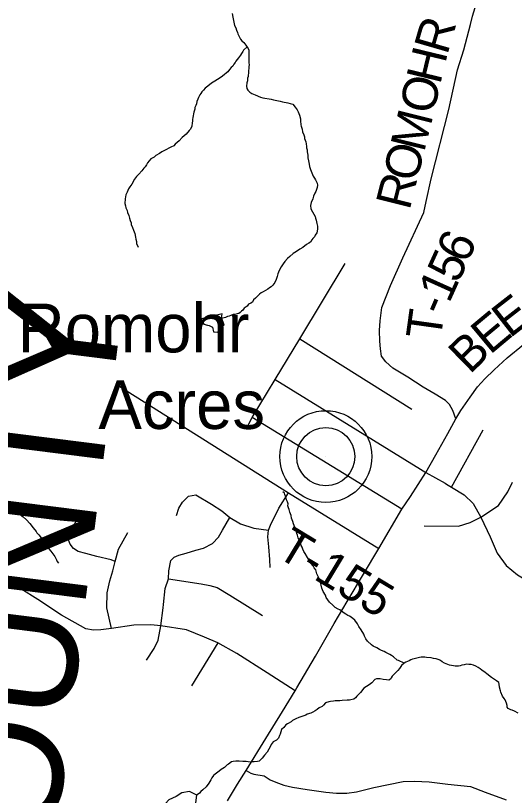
# Model space of a CAD drawing. Extents: x 0 to 34, y 0 to 22.
# Drawn here: x 6.117 to 6.521, y 17.744 to 18.376 of the extents above; entities that cross this region are included whole.
import ezdxf

# ---------------------------------------------------------------- set-up
doc = ezdxf.new("R2010")
doc.units = 0
for name, color, linetype in [('GM_X_County_Road', 7, 'Continuous'), ('GM_X_County_Road_Text', 7, 'Continuous'), ('GM_X_County_Text', 7, 'Continuous'), ('GM_X_Minor_Lake', 7, 'Continuous'), ('GM_X_Minor_River', 7, 'Continuous'), ('GM_X_Township_Road', 7, 'Continuous'), ('GM_X_Township_Road_Text', 7, 'Continuous'), ('GM_X_Unincorporated', 7, 'Continuous'), ('GM_X_Unincorporated_Location', 7, 'Continuous'), ('GM_X_Unincorporated_Text', 7, 'Continuous')]:
    doc.layers.add(name, color=color, linetype=linetype)

msp = doc.modelspace()

# ---------------------------------------------------------------- linework, layer by layer
at = {"layer": 'GM_X_County_Road'}
msp.add_lwpolyline([(6.28826, 17.73975), (6.29651, 17.75325), (6.30348, 17.76452), (6.31931, 17.79034), (6.33291, 17.81227), (6.34305, 17.82909), (6.34451, 17.8315), (6.3597, 17.85719), (6.37476, 17.88341), (6.38531, 17.90126), (6.39863, 17.92347), (6.41105, 17.94445), (6.42956, 17.97622), (6.43652, 17.98654), (6.44892, 18.00593), (6.45724, 18.02021), (6.46682, 18.03751), (6.47339, 18.04948), (6.47743, 18.05605), (6.4849, 18.06704), (6.49097, 18.07529), (6.49685, 18.08171), (6.50444, 18.08912), (6.51493, 18.09881), (6.52823, 18.10962)], dxfattribs=at)
at = {"layer": 'GM_X_Minor_Lake'}
for points in [[(6.2834, 18.1313), (6.28407, 18.13445), (6.26727, 18.13043), (6.26798, 18.12832), (6.26908, 18.12621), (6.2721, 18.12539), (6.27362, 18.12517), (6.27624, 18.12359), (6.27712, 18.11997)], [(6.27712, 18.11997), (6.28034, 18.11971), (6.28559, 18.12549), (6.28347, 18.13128)], [(6.26347, 17.74441), (6.25763, 17.74738), (6.25133, 17.74618), (6.24672, 17.74342), (6.24077, 17.7405), (6.23824, 17.73752), (6.23628, 17.73471), (6.23526, 17.7315), (6.2379, 17.7303), (6.24154, 17.73175), (6.24593, 17.7328), (6.24937, 17.73406), (6.25263, 17.73532), (6.25657, 17.73277), (6.26063, 17.73648), (6.26276, 17.73815), (6.26347, 17.74441)]]:
    msp.add_lwpolyline(points, dxfattribs=at)
at = {"layer": 'GM_X_Minor_River'}
for points in [[(6.29206, 18.3779), (6.29256, 18.37504), (6.29375, 18.3697), (6.2941, 18.36836), (6.29518, 18.36625), (6.29571, 18.36453), (6.29642, 18.36261), (6.29677, 18.36146), (6.29803, 18.35877), (6.29894, 18.35723), (6.30005, 18.35588), (6.30153, 18.35432), (6.30319, 18.35238), (6.30428, 18.35064), (6.3052, 18.34948), (6.30555, 18.34815), (6.30567, 18.34549), (6.30553, 18.33999), (6.30567, 18.33809), (6.30582, 18.33638), (6.30578, 18.33505), (6.30574, 18.33334), (6.30551, 18.33183), (6.30548, 18.33069), (6.30501, 18.32691), (6.30459, 18.32541), (6.30454, 18.32351), (6.30412, 18.32181), (6.30386, 18.31916), (6.304, 18.31707), (6.30472, 18.31573), (6.30658, 18.31416), (6.30807, 18.31298), (6.3107, 18.31197), (6.31522, 18.31014), (6.3171, 18.30952), (6.32372, 18.3084), (6.32561, 18.30797), (6.33109, 18.30688), (6.33297, 18.30645), (6.33732, 18.30558), (6.33901, 18.30497), (6.34128, 18.30453), (6.34331, 18.30201), (6.34477, 18.29988), (6.34568, 18.29834), (6.34675, 18.29566), (6.34744, 18.2926), (6.34758, 18.29089), (6.34788, 18.28785), (6.34804, 18.28652), (6.34874, 18.28422), (6.34926, 18.28212), (6.35014, 18.27963), (6.35068, 18.2781), (6.35083, 18.27677), (6.35171, 18.2739), (6.35204, 18.27219), (6.35237, 18.27009), (6.35234, 18.26895), (6.35287, 18.26742), (6.35302, 18.26571), (6.35333, 18.26305), (6.35347, 18.26096), (6.35397, 18.25848), (6.35413, 18.25715), (6.35448, 18.25581), (6.35481, 18.2539), (6.3555, 18.25142), (6.35711, 18.24739), (6.35765, 18.24624), (6.35875, 18.2445), (6.35966, 18.24315), (6.36057, 18.24161), (6.36111, 18.24046), (6.36126, 18.23875), (6.36102, 18.23686), (6.35999, 18.23366), (6.3592, 18.23235), (6.358, 18.22992), (6.35737, 18.22785), (6.35615, 18.22465), (6.35552, 18.2222), (6.35583, 18.21954), (6.35729, 18.21722), (6.35838, 18.2153), (6.35928, 18.21338), (6.35963, 18.21204), (6.36016, 18.21032), (6.36085, 18.20784), (6.36136, 18.20555), (6.36131, 18.20346), (6.36088, 18.20157), (6.36066, 18.20025), (6.35928, 18.1982), (6.35887, 18.19707)], [(6.30418, 18.35081), (6.30137, 18.34825), (6.30077, 18.34713), (6.29959, 18.34545), (6.29899, 18.34414), (6.29741, 18.34191), (6.29507, 18.33931), (6.29447, 18.33819), (6.29349, 18.33689), (6.29269, 18.33539), (6.29133, 18.3341), (6.28996, 18.33262), (6.28877, 18.33056), (6.28761, 18.32983), (6.28567, 18.32818), (6.28315, 18.32635), (6.28026, 18.32452), (6.27813, 18.32306), (6.27544, 18.32161), (6.27233, 18.31904), (6.2702, 18.31739), (6.26902, 18.31571), (6.26747, 18.31443), (6.26668, 18.31312), (6.26589, 18.312), (6.26548, 18.31087), (6.26488, 18.30975), (6.26428, 18.30844), (6.26366, 18.30675), (6.26323, 18.30467), (6.26282, 18.30335), (6.26202, 18.30167), (6.2618, 18.30054), (6.26116, 18.29809), (6.26094, 18.29676), (6.26051, 18.29488), (6.2603, 18.29375), (6.26006, 18.29204), (6.26003, 18.29072), (6.2598, 18.28921), (6.25936, 18.28675), (6.25834, 18.28412), (6.25736, 18.28301), (6.25482, 18.28023), (6.25172, 18.27747), (6.24918, 18.27469), (6.24588, 18.27193), (6.2449, 18.27081), (6.24259, 18.26974), (6.24144, 18.26901), (6.23836, 18.26757), (6.23527, 18.26575), (6.23334, 18.26448), (6.23026, 18.26285), (6.2289, 18.26156), (6.22639, 18.26011), (6.22483, 18.25844), (6.22366, 18.25695), (6.22285, 18.25527), (6.22168, 18.25378), (6.22069, 18.25248), (6.21893, 18.25044), (6.21659, 18.24784), (6.21464, 18.24581), (6.21306, 18.24357), (6.21087, 18.23964), (6.2093, 18.23741), (6.2083, 18.23573), (6.2071, 18.2331), (6.2061, 18.23104), (6.20545, 18.22784), (6.20534, 18.22385), (6.20568, 18.22214), (6.20602, 18.22042), (6.2071, 18.21831), (6.20744, 18.21659), (6.20851, 18.2141), (6.20903, 18.212), (6.20955, 18.21009), (6.21027, 18.20836), (6.21042, 18.20684), (6.2115, 18.20453), (6.2122, 18.20243), (6.21328, 18.19974), (6.21377, 18.1967), (6.21411, 18.19517), (6.21463, 18.19307), (6.21477, 18.19136), (6.21567, 18.18944), (6.21603, 18.18857)], [(6.35887, 18.19707), (6.3575, 18.19559), (6.35672, 18.19447), (6.35553, 18.19261), (6.35436, 18.19169), (6.35244, 18.1906), (6.34953, 18.18821), (6.34703, 18.18695), (6.34413, 18.18513), (6.34162, 18.1833), (6.3389, 18.18109), (6.33696, 18.17925), (6.33481, 18.17703), (6.33343, 18.17516), (6.33185, 18.17274), (6.33025, 18.16956), (6.32924, 18.16693), (6.32861, 18.16467), (6.32779, 18.16241), (6.32659, 18.15998), (6.3258, 18.15886), (6.3252, 18.15774), (6.32384, 18.15645), (6.32249, 18.15572), (6.32094, 18.15443), (6.31728, 18.15244), (6.31574, 18.15154), (6.31438, 18.15043), (6.31205, 18.14841), (6.31107, 18.14729), (6.30952, 18.14582), (6.30852, 18.14395), (6.30717, 18.14322), (6.30544, 18.14232), (6.30426, 18.14083), (6.30194, 18.139), (6.30076, 18.13751), (6.2996, 18.13678), (6.29862, 18.13548), (6.29746, 18.13475), (6.29631, 18.1344), (6.29421, 18.13389), (6.29307, 18.13392), (6.29097, 18.13321), (6.28962, 18.13268), (6.28848, 18.13233), (6.28674, 18.13143), (6.28464, 18.13091), (6.28332, 18.13133)], [(6.43136, 17.85143), (6.42685, 17.85345), (6.42573, 17.85385), (6.42276, 17.85659), (6.42126, 17.85758), (6.41976, 17.85837), (6.41657, 17.85997), (6.41527, 17.86077), (6.4132, 17.86177), (6.41151, 17.86257), (6.40945, 17.86377), (6.40626, 17.86518), (6.40515, 17.86634), (6.40181, 17.86928), (6.40052, 17.87102), (6.39925, 17.87333), (6.39891, 17.87486), (6.39673, 17.87852), (6.39471, 17.88122), (6.39381, 17.88333), (6.39142, 17.88624), (6.38863, 17.88859), (6.38713, 17.88939), (6.38581, 17.88999), (6.38432, 17.89098), (6.38282, 17.89178), (6.37928, 17.89453), (6.37797, 17.89513), (6.37572, 17.89652), (6.37368, 17.89828), (6.3709, 17.90082), (6.36834, 17.90468), (6.36763, 17.90659), (6.3658, 17.90949), (6.36473, 17.91217), (6.36336, 17.91828), (6.36174, 17.92155), (6.36085, 17.92385), (6.36014, 17.92595), (6.35998, 17.92709), (6.35869, 17.92865), (6.35778, 17.93038), (6.35575, 17.93252), (6.35502, 17.93367), (6.35393, 17.93579), (6.3532, 17.93695), (6.35139, 17.94022), (6.35029, 17.94195), (6.34939, 17.94388), (6.34886, 17.94541), (6.34814, 17.94675), (6.34707, 17.94963), (6.34564, 17.95308), (6.34512, 17.95518), (6.3444, 17.95653), (6.34388, 17.95882), (6.34336, 17.96054), (6.34228, 17.96284), (6.34175, 17.96437), (6.34142, 17.96628), (6.34034, 17.96896), (6.33983, 17.97106), (6.33895, 17.97374), (6.33824, 17.97604), (6.33771, 17.97738), (6.33737, 17.97891), (6.33741, 17.98061), (6.33688, 17.98214), (6.33617, 17.98387), (6.336, 17.98501), (6.33529, 17.98674), (6.33494, 17.98807), (6.33459, 17.98922), (6.33329, 17.99021)], [(6.11621, 17.97483), (6.11938, 17.97266), (6.1205, 17.97187), (6.12293, 17.9701), (6.12552, 17.96756), (6.12829, 17.96446), (6.13086, 17.96097), (6.13345, 17.95806), (6.13398, 17.95691), (6.13547, 17.95535), (6.1373, 17.95284), (6.13765, 17.95169), (6.13931, 17.94956), (6.1417, 17.94646), (6.14243, 17.94531), (6.14373, 17.94413), (6.14539, 17.94219), (6.14685, 17.93988), (6.14851, 17.93794), (6.14977, 17.93525), (6.15049, 17.9339), (6.15159, 17.93236)], [(6.52377, 17.81088), (6.52077, 17.81248), (6.51889, 17.81329), (6.51776, 17.81369), (6.51569, 17.81451), (6.51497, 17.81585), (6.51481, 17.817), (6.51447, 17.8189), (6.51375, 17.82025), (6.51321, 17.82159), (6.51248, 17.82275), (6.5112, 17.82468), (6.50976, 17.82775), (6.5096, 17.82889), (6.50873, 17.83195), (6.50841, 17.83443), (6.50826, 17.83576), (6.50639, 17.83695), (6.50228, 17.83971), (6.49856, 17.84284), (6.49707, 17.84383), (6.49445, 17.84561), (6.49296, 17.84678), (6.49147, 17.84777), (6.4896, 17.84896), (6.48772, 17.84977), (6.48564, 17.8502), (6.48375, 17.85044), (6.48185, 17.85049), (6.47995, 17.85016), (6.47822, 17.84964), (6.47688, 17.8491), (6.47536, 17.84895), (6.47403, 17.84899), (6.4727, 17.84902), (6.47157, 17.84924), (6.46986, 17.84947), (6.46816, 17.8499), (6.46553, 17.85073), (6.46421, 17.85133), (6.46234, 17.85252), (6.46104, 17.8535), (6.45991, 17.8541), (6.45728, 17.85493), (6.45519, 17.85517), (6.45331, 17.8556), (6.44952, 17.85608), (6.4482, 17.8563), (6.44516, 17.85619), (6.44401, 17.85603), (6.44172, 17.85552), (6.43962, 17.85501), (6.43828, 17.85466), (6.43694, 17.85413), (6.4354, 17.85341), (6.43424, 17.85268), (6.43271, 17.85215), (6.43136, 17.85143), (6.42922, 17.8494), (6.42764, 17.84716), (6.42627, 17.84549), (6.42452, 17.84364), (6.42315, 17.84216), (6.42179, 17.84087), (6.42099, 17.83956), (6.4204, 17.83844), (6.41905, 17.83771), (6.41715, 17.83776), (6.4145, 17.83802), (6.41205, 17.83866), (6.40901, 17.83874), (6.40767, 17.8382), (6.40532, 17.83542), (6.403, 17.83396), (6.39875, 17.83123), (6.39619, 17.8275), (6.39307, 17.82454), (6.39209, 17.82324), (6.39074, 17.82233), (6.38825, 17.82164), (6.38711, 17.82148)], [(6.38711, 17.82148), (6.3854, 17.82133), (6.38121, 17.82106), (6.3795, 17.82092), (6.3757, 17.82083), (6.37418, 17.82068), (6.3717, 17.82036), (6.37036, 17.82002), (6.36787, 17.81913), (6.36611, 17.81728), (6.36495, 17.81636), (6.36264, 17.8151), (6.3609, 17.81382), (6.35935, 17.81272), (6.35761, 17.81162), (6.35589, 17.81091), (6.35301, 17.81004), (6.35186, 17.80931), (6.34764, 17.8079), (6.34611, 17.80737), (6.34361, 17.8063), (6.34111, 17.80485), (6.33995, 17.80393), (6.33686, 17.80211), (6.3357, 17.80138), (6.33394, 17.79934), (6.33218, 17.79749), (6.33095, 17.79392), (6.33055, 17.79279), (6.32973, 17.79073), (6.32817, 17.78887), (6.32548, 17.78761), (6.32371, 17.78538), (6.32291, 17.7837), (6.32191, 17.78164), (6.32052, 17.77921), (6.31836, 17.7768), (6.3164, 17.77438), (6.31524, 17.77327), (6.31406, 17.77198), (6.31273, 17.77163), (6.31006, 17.77132), (6.30854, 17.77136), (6.30664, 17.77122), (6.30342, 17.77169), (6.30077, 17.77176), (6.29792, 17.77202), (6.29508, 17.77209), (6.29298, 17.77177), (6.29164, 17.77142), (6.28912, 17.7694), (6.28797, 17.76886), (6.28583, 17.76683), (6.28332, 17.76519), (6.28157, 17.76372), (6.27829, 17.76153), (6.27711, 17.76023), (6.27574, 17.75856), (6.27494, 17.75688), (6.27335, 17.75426), (6.27099, 17.7511), (6.26846, 17.7487), (6.26672, 17.74741), (6.26574, 17.74611), (6.2638, 17.74465), (6.26347, 17.74441)]]:
    msp.add_lwpolyline(points, dxfattribs=at)
at = {"layer": 'GM_X_Township_Road'}
for p, q in [((6.34694, 18.11432), (6.3837, 18.17522)), ((6.34694, 18.11432), (6.43756, 18.05731)), ((6.32706, 18.08139), (6.44471, 18.00853)), ((6.42956, 17.97622), (6.30834, 18.05037)), ((6.46989, 17.99402), (6.4954, 18.04051)), ((6.28043, 17.86784), (6.2592, 17.83299))]:
    msp.add_line(p, q, dxfattribs=at)
for points in [[(6.47339, 18.04948), (6.47091, 18.05615), (6.46821, 18.06097), (6.46492, 18.0643), (6.45651, 18.06948), (6.44694, 18.07514), (6.43451, 18.08327), (6.42226, 18.09046), (6.41668, 18.09551), (6.41318, 18.10014), (6.41221, 18.10625), (6.41182, 18.11231), (6.41162, 18.12102), (6.41202, 18.12874), (6.41348, 18.1397), (6.42052, 18.1574), (6.4303, 18.17979), (6.44732, 18.21666), (6.44927, 18.22546), (6.45328, 18.24404), (6.46776, 18.30017), (6.4748, 18.33234), (6.47978, 18.34857), (6.48526, 18.36901), (6.48692, 18.37585), (6.48897, 18.3827)], [(6.30421, 18.04257), (6.30834, 18.05037), (6.32706, 18.08139), (6.34694, 18.11432)], [(6.2011, 18.0757), (6.33776, 17.98933), (6.41105, 17.94445)], [(6.44471, 18.00853), (6.44892, 18.00593), (6.46461, 17.99724), (6.46583, 17.9965)], [(6.44755, 17.96264), (6.47537, 17.96248), (6.48504, 17.96548), (6.49353, 17.96981), (6.50786, 17.97914), (6.51536, 17.99013), (6.51919, 17.99796)], [(6.46583, 17.9965), (6.46989, 17.99402), (6.48013, 17.98775), (6.48737, 17.9808), (6.49353, 17.96981), (6.50103, 17.95381), (6.50686, 17.94065), (6.51419, 17.93049), (6.52319, 17.92299), (6.53718, 17.9145), (6.54635, 17.91083), (6.55634, 17.911), (6.56211, 17.91348), (6.5695, 17.91766), (6.57817, 17.92416), (6.58934, 17.93412), (6.59891, 17.94153), (6.60973, 17.9491), (6.61807, 17.95204), (6.62595, 17.95296), (6.63707, 17.95065), (6.64603, 17.94787), (6.67816, 17.94014), (6.68571, 17.93846)], [(6.32282, 17.92904), (6.32269, 17.93549), (6.32179, 17.94567), (6.32114, 17.95366), (6.32162, 17.95922), (6.32326, 17.96331), (6.32991, 17.97692), (6.33776, 17.98933)], [(6.24715, 17.97094), (6.24896, 17.97713), (6.25192, 17.9819), (6.25669, 17.98679), (6.26271, 17.98785), (6.27551, 17.98035), (6.28376, 17.97481), (6.2902, 17.96939), (6.29897, 17.96436), (6.30967, 17.96088), (6.32162, 17.95922)], [(6.19737, 17.93367), (6.19416, 17.9352), (6.18245, 17.93785), (6.17366, 17.94022), (6.16752, 17.94176), (6.16362, 17.94427), (6.16097, 17.94775), (6.15902, 17.95263), (6.16041, 17.9578), (6.16446, 17.96393), (6.16752, 17.96951), (6.17101, 17.97453)], [(6.2438, 17.936), (6.24509, 17.93729), (6.24896, 17.93884), (6.25488, 17.94052), (6.26275, 17.94296), (6.2688, 17.94451), (6.27628, 17.94825), (6.28105, 17.95354), (6.28427, 17.95908), (6.2902, 17.96939)], [(6.19437, 17.87945), (6.1907, 17.89616), (6.19095, 17.9085), (6.19318, 17.91805), (6.19541, 17.92628), (6.19737, 17.93367), (6.20002, 17.94385), (6.20755, 17.95724)], [(6.23614, 17.89621), (6.23647, 17.89882), (6.2379, 17.91204), (6.24064, 17.91977), (6.24083, 17.92616), (6.24251, 17.93471), (6.2438, 17.936)], [(6.24064, 17.91977), (6.26696, 17.91568), (6.27393, 17.91442), (6.28006, 17.91261), (6.29039, 17.90648), (6.3166, 17.89002)], [(6.34305, 17.82909), (6.32053, 17.84348), (6.29592, 17.85909), (6.28043, 17.86784), (6.26969, 17.87246), (6.2552, 17.87833), (6.23434, 17.8817), (6.22622, 17.88258), (6.21248, 17.8822), (6.19437, 17.87945), (6.18575, 17.87845), (6.17976, 17.87808), (6.17364, 17.87933), (6.15386, 17.8903), (6.13461, 17.90299), (6.12094, 17.91177)], [(6.22272, 17.85371), (6.2291, 17.86321), (6.23234, 17.86996), (6.23434, 17.8817), (6.23614, 17.89621)], [(6.30348, 17.76452), (6.30715, 17.76232), (6.30972, 17.76145), (6.31795, 17.76003), (6.323, 17.75688), (6.3275, 17.75489), (6.33408, 17.75248), (6.34106, 17.75101), (6.35295, 17.74906), (6.36805, 17.74686), (6.37675, 17.74592), (6.38509, 17.74614), (6.39287, 17.74712), (6.40696, 17.75064), (6.41874, 17.75296), (6.43066, 17.75547), (6.43976, 17.75578), (6.45168, 17.75516), (6.46674, 17.75327), (6.4852, 17.75135), (6.49704, 17.74693), (6.51412, 17.74072)]]:
    msp.add_lwpolyline(points, dxfattribs=at)
at = {"layer": 'GM_X_Unincorporated'}
for radius in [0.0372, 0.02358]:
    msp.add_circle((6.36801, 18.01881), radius, dxfattribs=at)
at = {"layer": 'GM_X_Unincorporated_Location'}
msp.add_line((6.36801, 18.01881), (6.36801, 18.01881), dxfattribs=at)

# ---------------------------------------------------------------- texts
at = {"layer": 'GM_X_County_Road_Text'}
for s, rotation, p in [('E', 37.91821, (6.51702, 18.11433)), ('E', 39.89007, (6.50092, 18.10087)), ('B', 44.30726, (6.48465, 18.08496))]:
    msp.add_text(s, height=0.02841, rotation=rotation, dxfattribs=at).set_placement(p)
at = {"layer": 'GM_X_County_Text'}
msp.add_text('CLERMONT COUNTY', height=0.094697, rotation=82.79761, dxfattribs=at).set_placement((6.04352, 16.87439))
at = {"layer": 'GM_X_Township_Road_Text'}
for s, height, rotation, p in [('R', 0.02841, 73.78225, (6.46637, 18.34368)), ('H', 0.02841, 76.40196, (6.46058, 18.31971)), ('O', 0.02841, 77.49885, (6.4552, 18.29545)), ('M', 0.02841, 76.01977, (6.44757, 18.26475)), ('O', 0.02841, 75.90279, (6.44146, 18.24044)), ('R', 0.02841, 75.90506, (6.43578, 18.21781)), ('6', 0.02841, 65.51598, (6.48227, 18.1743)), ('5', 0.02841, 65.55087, (6.47503, 18.15837)), ('1', 0.02841, 65.73262, (6.46785, 18.14244)), ('-', 0.02841, 66.89673, (6.46333, 18.13185)), ('T', 0.02841, 82.08929, (6.46094, 18.11271)), ('T-155', 0.028409, 328.79533, (6.32657, 17.93866))]:
    msp.add_text(s, height=height, rotation=rotation, dxfattribs=at).set_placement(p)
at = {"layer": 'GM_X_Unincorporated_Text'}
for s, p in [('Romohr', (6.11837, 18.10331)), ('Acres', (6.18379, 18.04123))]:
    msp.add_text(s, height=0.039489, rotation=0.00001, dxfattribs=at).set_placement(p)

doc.saveas('drawing.dxf')
